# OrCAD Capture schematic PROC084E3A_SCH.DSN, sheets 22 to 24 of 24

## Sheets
22 22. RMII_INTERFACE: size C; title: RMII INTERFACE
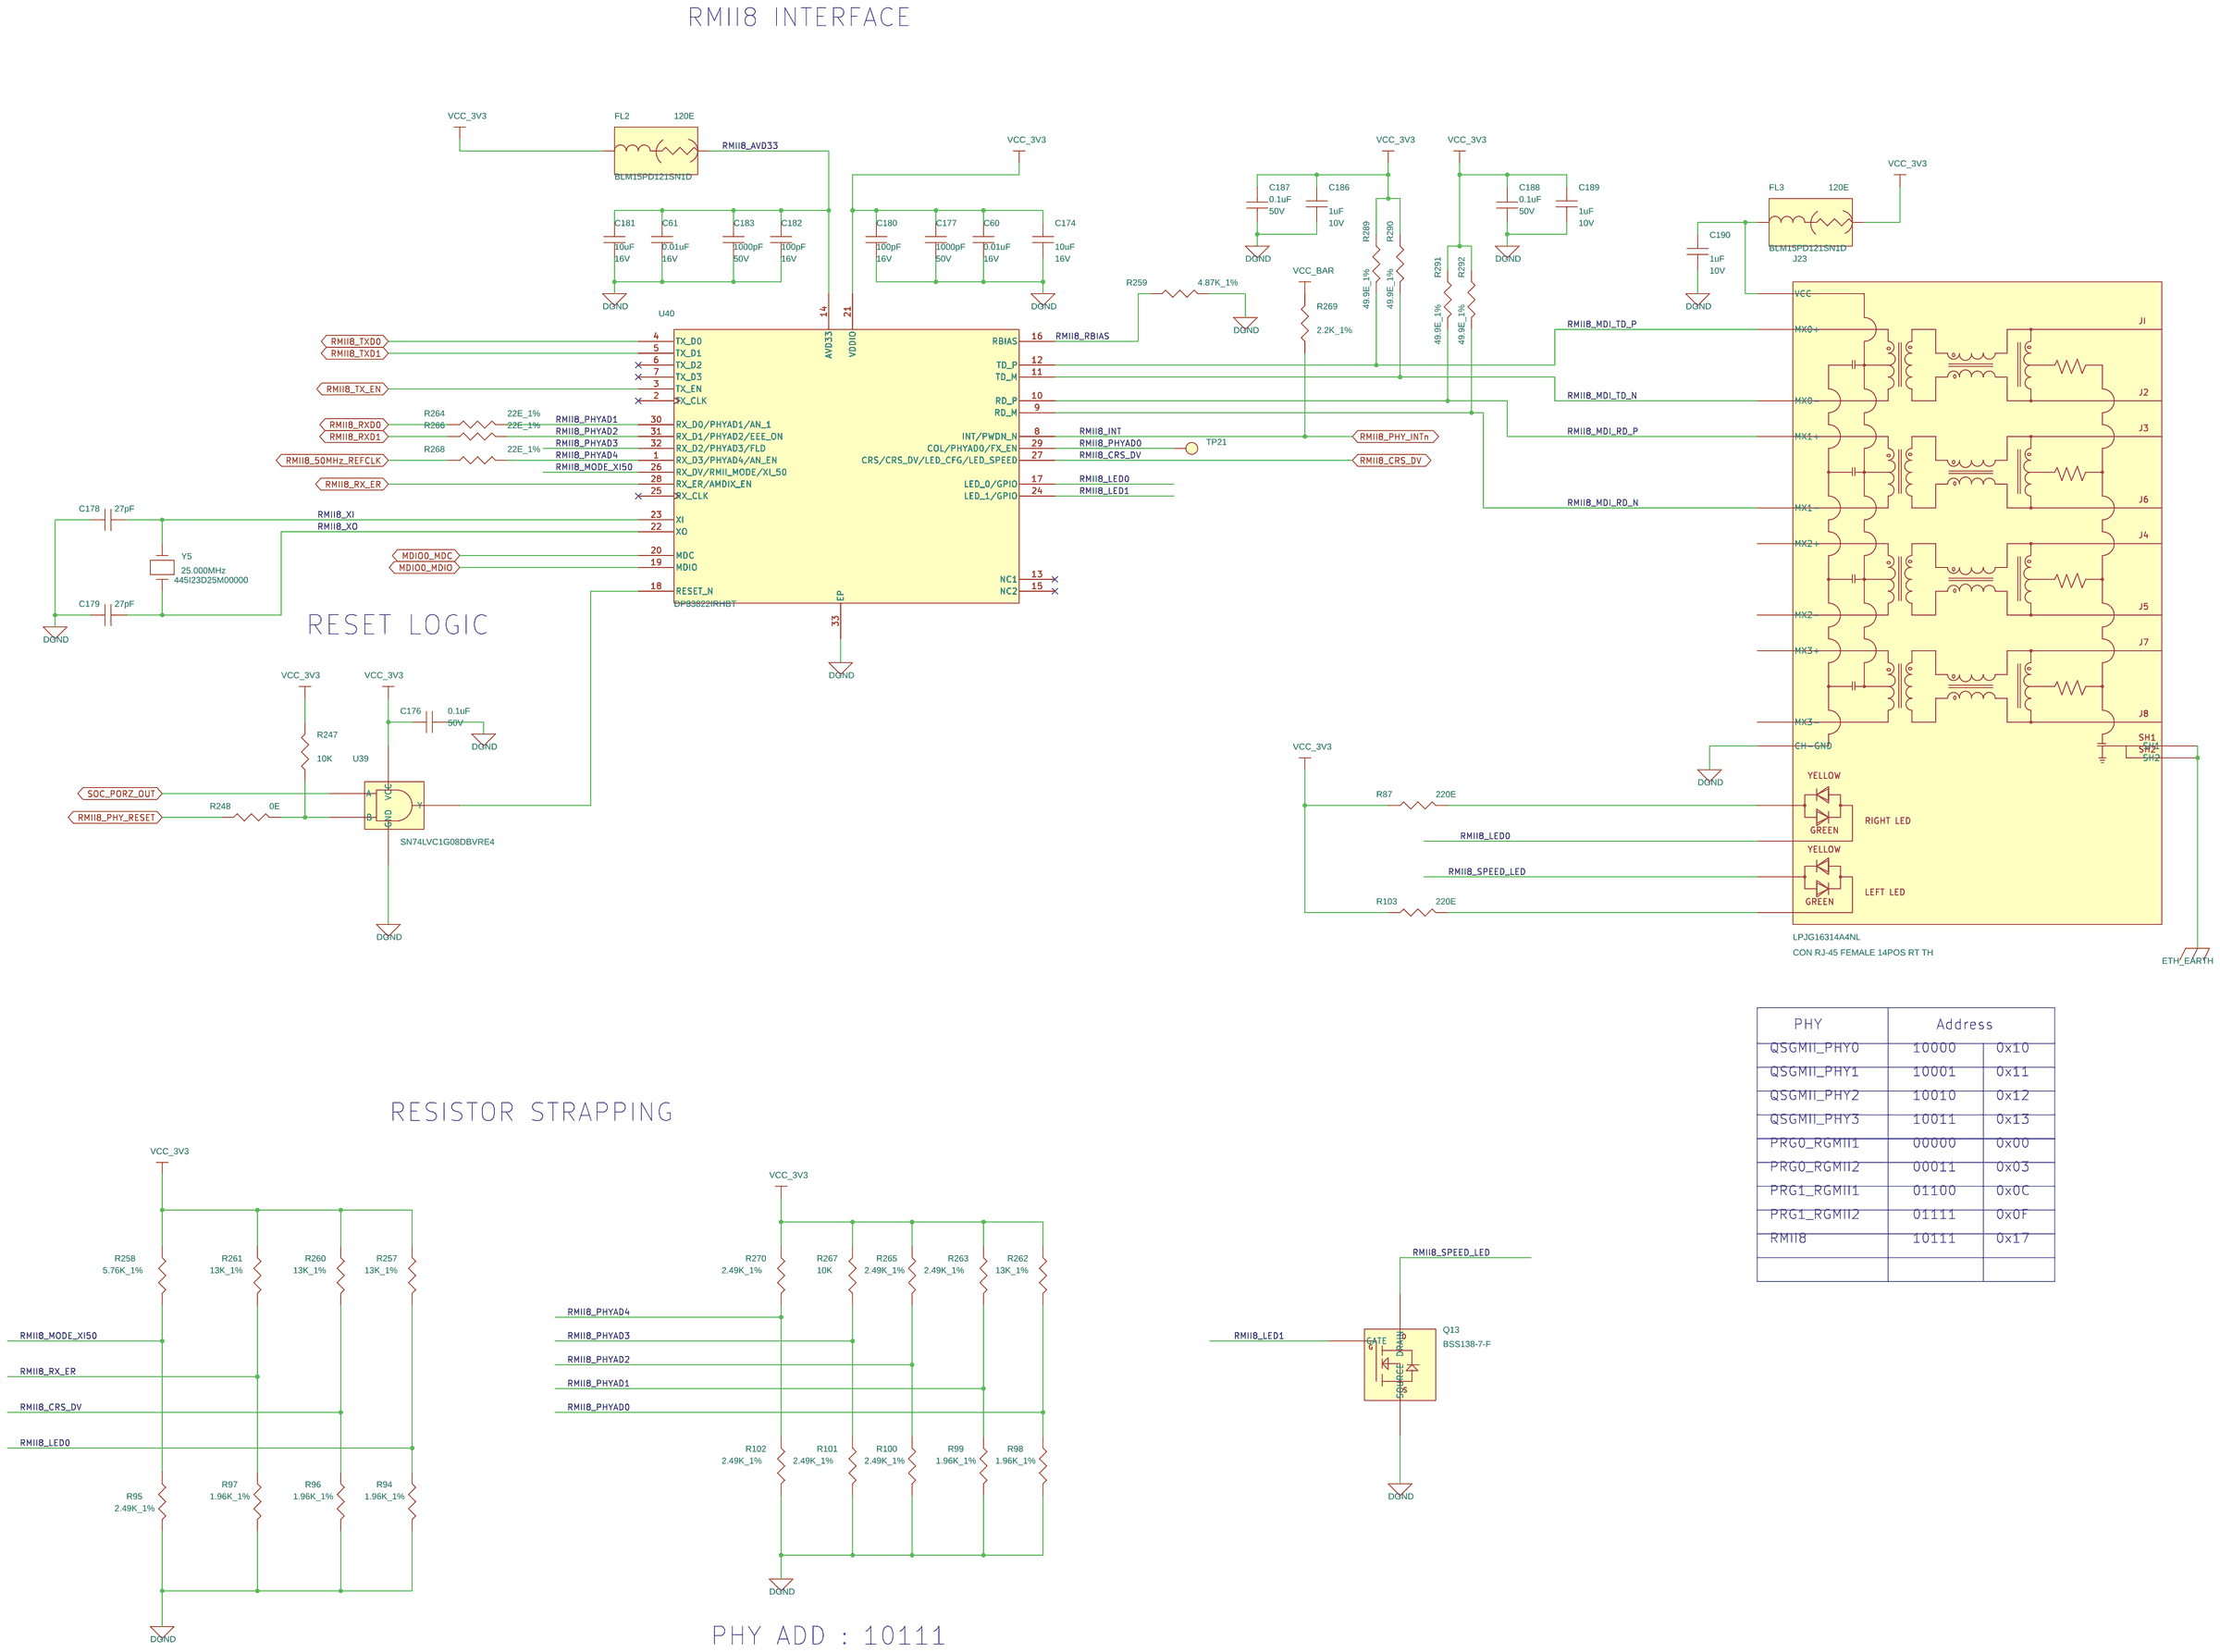
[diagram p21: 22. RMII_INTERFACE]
23 23. POWER SUPPLY: size C; title: P0WER SUPPLY
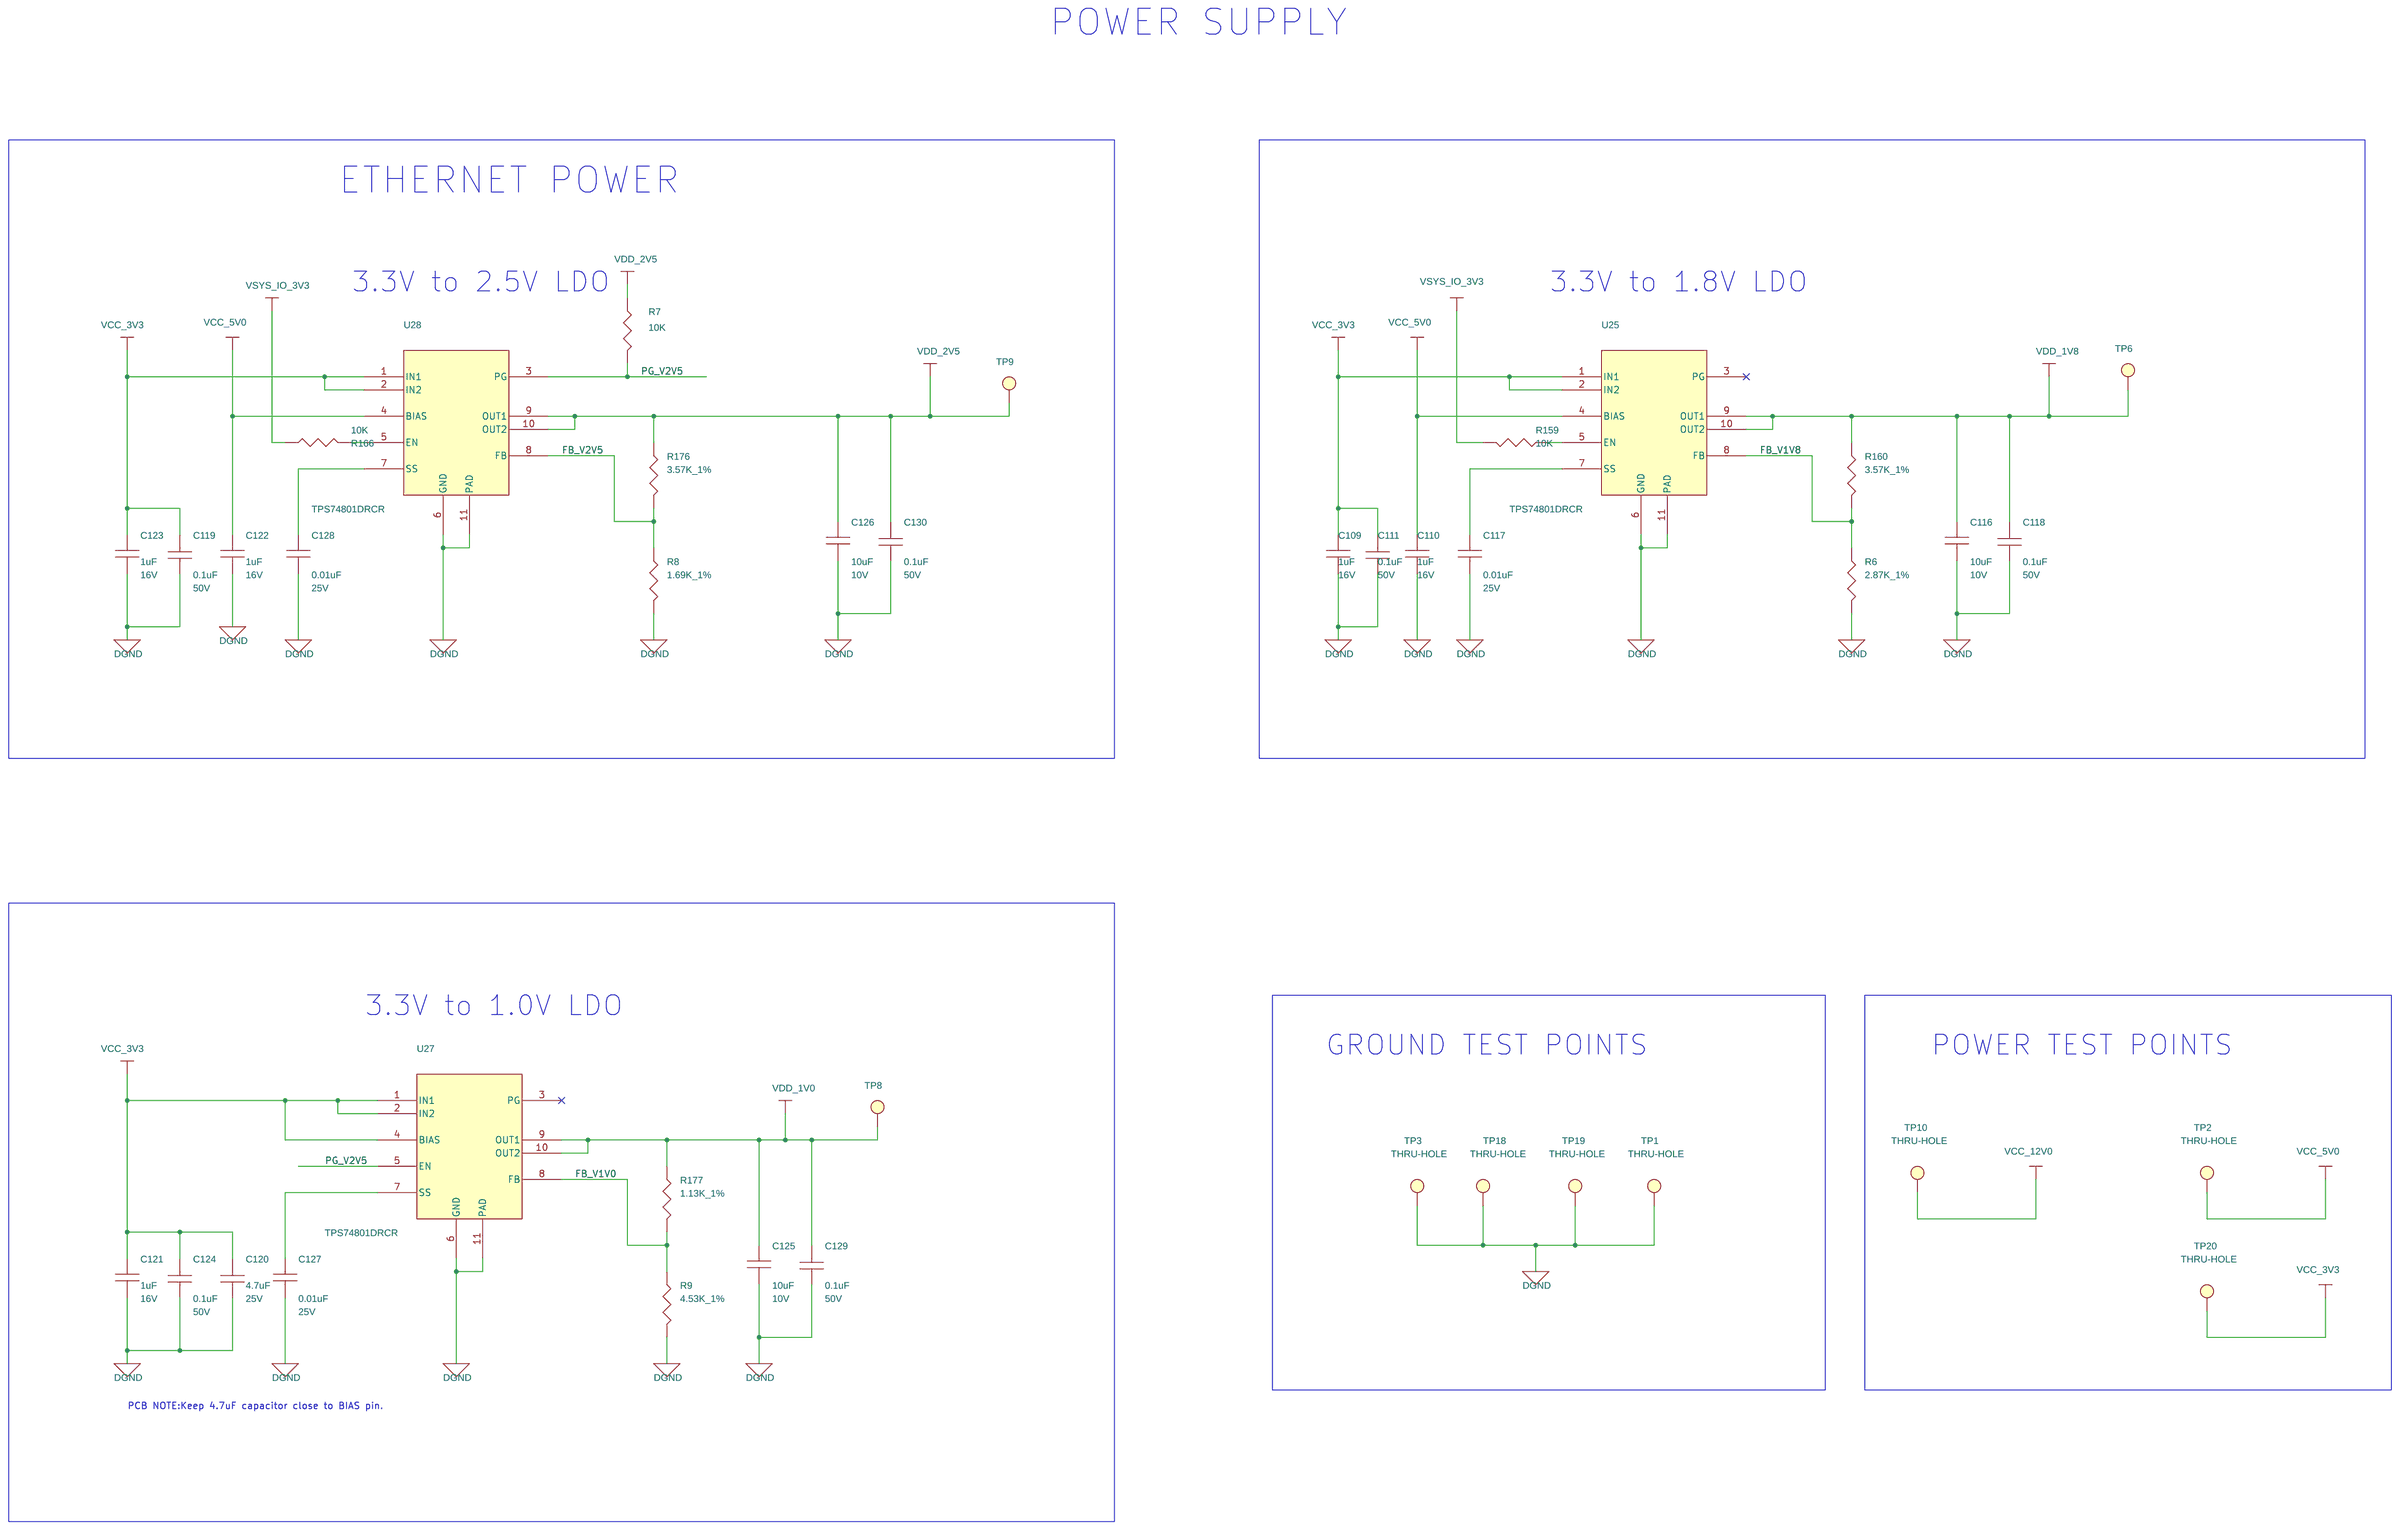
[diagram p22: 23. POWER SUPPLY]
24 19. USS/IMU & MOTOR CONTROL: size C; title: USS/IMU & MOTOR CONTROL
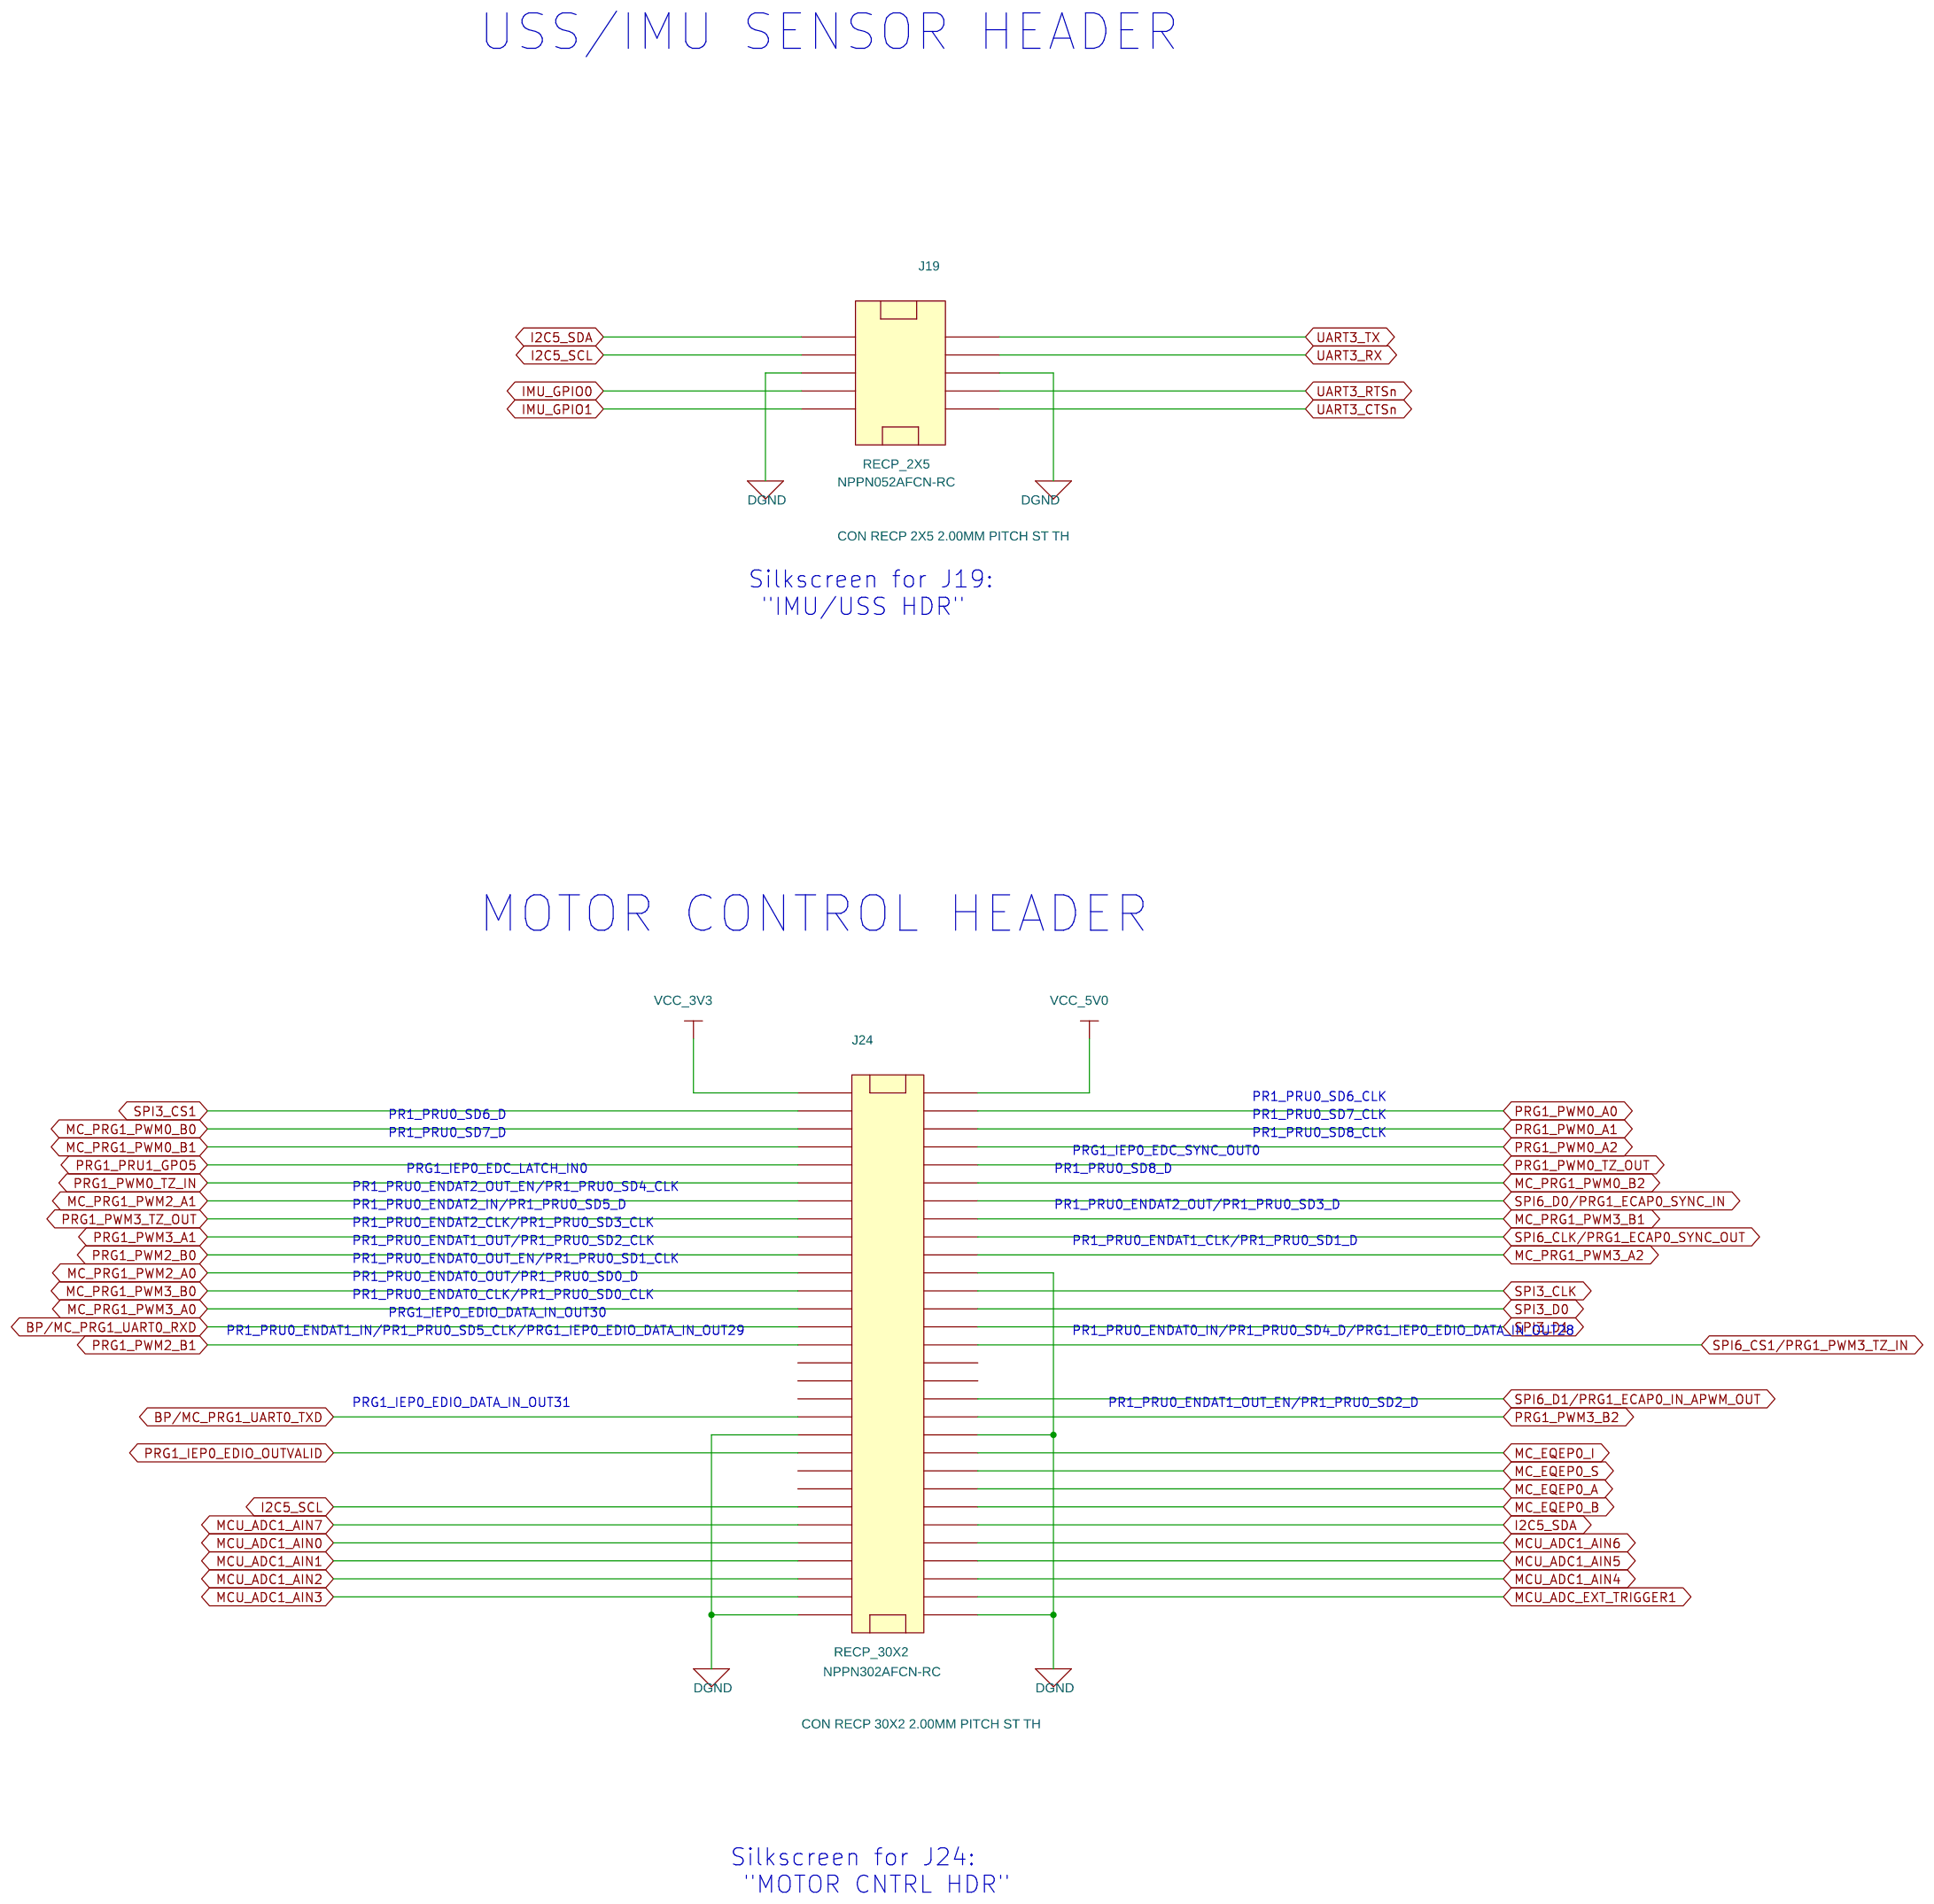
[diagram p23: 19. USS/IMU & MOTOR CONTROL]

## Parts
sheet 19. USS/IMU & MOTOR CONTROL
J19  RECP_2X5  [RECPT_2X5_NPPN052AFCN_S_T_4-3]
J24  RECP_30X2  [RECPT_2X30_78-74_S_T]
sheet 22. RMII_INTERFACE
C60  0.01uF  [CAP0402_0-75]
C61  0.01uF  [CAP0402_0-75]
C174  10uF  [CAP0805_1-5]
C176  0.1uF  [CAP0402_0-75]
C177  1000pF  [CAP0402_0-75]
C178  27pF  [CAP0402_0-75]
C179  27pF  [CAP0402_0-75]
C180  100pF  [CAP0402_0-75]
C181  10uF  [CAP0805_1-5]
C182  100pF  [CAP0402_0-75]
C183  1000pF  [CAP0402_0-75]
C186  1uF  [CAP0402_0-75]
C187  0.1uF  [CAP0402_0-75]
C188  0.1uF  [CAP0402_0-75]
C189  1uF  [CAP0402_0-75]
C190  1uF  [CAP0402_0-75]
FL2  120E  [EMIFIL_BLM15A_0402_0-6]
FL3  120E  [EMIFIL_BLM15A_0402_0-6]
J23  CON_RJ45-14_LPJG16314A4NL  [CON_RJ45-14_LPJG16314A4NL_S_R_T_13-6]
Q13  BSS138-7-F  [SOT23-123_1-1]
R87  220E  [RES0603_0-75]
R94  1.96K_1%  [RES0402_0-5]
R95  2.49K_1%  [RES0402_0-5]
R96  1.96K_1%  [RES0402_0-5]
R97  1.96K_1%  [RES0402_0-5]
R98  1.96K_1%  [RES0402_0-5]
R99  1.96K_1%  [RES0402_0-5]
R100  2.49K_1%  [RES0402_0-5]
R101  2.49K_1%  [RES0402_0-5]
R102  2.49K_1%  [RES0402_0-5]
R103  220E  [RES0603_0-75]
R247  10K  [RES0402_0-5]
R248  0E  [RES0402_0-5]
R257  13K_1%  [RES0402_0-5]
R258  5.76K_1%  [RES0402_0-5]
R259  4.87K_1%  [RES0402_0-5]
R260  13K_1%  [RES0402_0-5]
R261  13K_1%  [RES0402_0-5]
R262  13K_1%  [RES0402_0-5]
R263  2.49K_1%  [RES0402_0-5]
R264  22E_1%  [RES0402_0-5]
R265  2.49K_1%  [RES0402_0-5]
R266  22E_1%  [RES0402_0-5]
R267  10K  [RES0402_0-5]
R268  22E_1%  [RES0402_0-5]
R269  2.2K_1%  [RES0402_0-5]
R270  2.49K_1%  [RES0402_0-5]
R289  49.9E_1%  [RES0402_0-5]
R290  49.9E_1%  [RES0402_0-5]
R291  49.9E_1%  [RES0402_0-5]
R292  49.9E_1%  [RES0402_0-5]
TP21  TP40_SMD  [TP40_SMD]
U39  SN74LVC1G08DBVRE4  [SOT23-5]
U40  DP83822IRHBT  [QFN32_19-68_200X200_1]
Y5  25.000MHz  [XTAL_ABM3_205X130_SMD_1-4]
sheet 23. POWER SUPPLY
C109  1uF  [CAP0402_0-5]
C110  1uF  [CAP0402_0-5]
C111  0.1uF  [CAP0402_0-75]
C116  10uF  [CAP0402_0-75]
C117  0.01uF  [CAP0402_0-75]
C118  0.1uF  [CAP0402_0-75]
C119  0.1uF  [CAP0402_0-75]
C120  4.7uF  [CAP0603_1]
C121  1uF  [CAP0402_0-5]
C122  1uF  [CAP0402_0-5]
C123  1uF  [CAP0402_0-5]
C124  0.1uF  [CAP0402_0-75]
C125  10uF  [CAP0402_0-75]
C126  10uF  [CAP0402_0-75]
C127  0.01uF  [CAP0402_0-75]
C128  0.01uF  [CAP0402_0-75]
C129  0.1uF  [CAP0402_0-75]
C130  0.1uF  [CAP0402_0-75]
R6  2.87K_1%  [RES0402_0-5]
R7  10K  [RES0402_0-5]
R8  1.69K_1%  [RES0402_0-5]
R9  4.53K_1%  [RES0402_0-5]
R159  10K  [RES0402_0-5]
R160  3.57K_1%  [RES0402_0-5]
R166  10K  [RES0402_0-5]
R176  3.57K_1%  [RES0402_0-5]
R177  1.13K_1%  [RES0402_0-5]
TP1  THRU HOLE  [TP_40X65]
TP2  THRU HOLE  [TP_40X65]
TP3  THRU HOLE  [TP_40X65]
TP6  THRU HOLE  [TP_40X65]
TP8  THRU HOLE  [TP_40X65]
TP9  THRU HOLE  [TP_40X65]
TP10  THRU HOLE  [TP_40X65]
TP18  THRU HOLE  [TP_40X65]
TP19  THRU HOLE  [TP_40X65]
TP20  THRU HOLE  [TP_40X65]
U25  TPS74801DRCR  [VSON10_TPS74801-Q1_120X120_1]
U27  TPS74801DRCR  [VSON10_TPS74801-Q1_120X120_1]
U28  TPS74801DRCR  [VSON10_TPS74801-Q1_120X120_1]

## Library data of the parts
J19 = RECP_5X2: CON RECP 2X5 2.00MM PITCH ST TH; Chkd/date: MANIRAJA/281218; Crtd /date: MANIRAJA/281218; Custom_Duty: 24%; Customs_HS_Code: 85369090; Distributor_name: DIGIKEY; Distributor_part_number: S5750-05-ND; Footprint Path: Y:\MIS_DATABASE\Library\ALTIUM_TOOL\PCB_FOOTPRINTS\Altium_Footprint_Lib.PcbLib; Height: 4.30MM; Library Path: Y:\MIS_DATABASE\Library\ALTIUM_TOOL\SCHEMATICS_PARTS\MS_CONNECTOR_Library.schlib; Mfr_name: SULLINS ELECTRONICS; Mfr_part_number: NPPN052AFCN-RC; Mistral Part No: 150018120018-R; Package: THRU-HOLE; Part_type: CONNECTOR\RECEPTACLE; Project: TI_J7ES_GESI_EXP; RoHS: RoHS; Temperature: -40°C+105°C; Tolerance: NA; Voltage: NA; Wattage: NA; Weight: NA; Datasheet: Y:\MIS_DATABASE\DATASHEETS\CONNECTORS\XPPNXX2AFCN-RC.PDF
J24 = RECP_30X2: CON RECP 30X2 2.00MM PITCH ST TH; Chkd/date: NAVEED/060815; Crtd /date: NAVEED/170914; Distributor_name: DIGIKEY; Distributor_part_number: S5750-30-ND; Height: 4.30MM; Mfr_name: SULLINS CONNECTOR; Mfr_part_number: NPPN302AFCN-RC; Mistral Part No: 150014090014-R; Package: THRU-HOLE; Part_type: CONNECTOR\RECEPTACLE; Project: AEGIS_POM; RoHS: RoHS; Temperature: -40°C+105°C; Tolerance: NA; Voltage: NA; Wattage: NA; Weight: NA; Datasheet: Y:\MIS_DATABASE\DATASHEETS\CONNECTORS\NPPNXXX.PDF
C60 C61 = CAP: CAP CERAMIC 0.01uF 16V 5% X7R 0402; Chkd/date: MANIRAJA/160519; Crtd /date: ALVY/160519; Custom_Duty: 15%; Customs_HS_Code: 85322990; Distributor_name: DIGIKEY; Distributor_part_number: 1276-1496-1-ND; Footprint Path: Y:\MIS_DATABASE\Library\ALTIUM_TOOL\PCB_FOOTPRINTS\Altium_Footprint_Lib.PcbLib; Height: 0.55MM; Library Path: Y:\MIS_DATABASE\Library\ALTIUM_TOOL\SCHEMATICS_PARTS\MS_DISCRETE_Library.schlib; Mfr_name: SAMSUNG; Mfr_part_number: CL05B103JO5NNNC; Mistral Part No: 120009030024-R; Package: 0402; Part_type: CAPACITORS\CERAMIC; Project: J7ES_SOM_DUAL-LEO_PMIC; RoHS: RoHS; Temperature: -55°C+125°C; Tolerance: 5%; Voltage: 16V; Wattage: NA; Weight: NA; Datasheet: Y:\MIS_DATABASE\DATASHEETS\CAPACITORS\CL05B103JO5NNNC.PDF
C174 C181 = CAP: CAP CERAMIC 10uF 16V 10% X5R 0805; Chkd/date: SHREESHAIL/220506; Crtd /date: MAZHAR/150506; Custom_Duty: 15%; Customs_HS_Code: 85322990; Distributor_name: DIGIKEY; Distributor_part_number: 490-3886-1-ND; Footprint Path: Y:\MIS_DATABASE\Library\ALTIUM_TOOL\PCB_FOOTPRINTS\Altium_Footprint_Lib.PcbLib; Height: 1.35MM; Library Path: Y:\MIS_DATABASE\Library\ALTIUM_TOOL\SCHEMATICS_PARTS\MS_DISCRETE_Library.schlib; Mfr_name: MURATA; Mfr_part_number: GRM21BR61C106KE15L; Mistral Part No: 120009030205-R; Package: 0805; Part_type: CAPACITORS\CERAMIC; Project: VOCERA; RoHS: RoHS; Temperature: -55°C+85°C; Tolerance: 10%; Voltage: 16V; Wattage: NA; Weight: 9.5mg; Datasheet: Y:\MIS_DATABASE\DATASHEETS\CAPACITORS\MURATA-GXX-SER_NOV17.PDF
C111 C118 C119 C124 C129 C130 C176 C187 C188 = CAP: CAP CERAMIC 0.1uF 50V 10% X7R 0402; Chkd/date: VASANTHA/281216; Crtd /date: CHAITHANYA/051011; Custom_Duty: 15%; Customs_HS_Code: 85322990; Distributor_name: DIGIKEY; Distributor_part_number: 445-173610-1-ND; Footprint Path: Y:\MIS_DATABASE\Library\ALTIUM_TOOL\PCB_FOOTPRINTS\Altium_Footprint_Lib.PcbLib; Height: 0.60MM; Library Path: Y:\MIS_DATABASE\Library\ALTIUM_TOOL\SCHEMATICS_PARTS\MS_DISCRETE_Library.schlib; Mfr_name: TDK CORPORATION; Mfr_part_number: C1005X7R1H104K050BE; Mistral Part No: 120011100014-R; Package: 0402; Part_type: CAPACITORS\CERAMIC; Project: VP-4000-BASE-BOARD; RoHS: RoHS; Temperature: -55°C+125°C; Tolerance: 10%; Voltage: 50V; Wattage: NA; Weight: 0.65mg; Datasheet: Y:\MIS_DATABASE\DATASHEETS\CAPACITORS\TDK_C-SER_FEB19.PDF
C177 C183 = CAP: CAP CERAMIC 1000pF 50V 5% X7R 0402; Chkd/date: VASANTHA/231216; Crtd /date: BAVISH/090611; Custom_Duty: 15%; Customs_HS_Code: 85322990; Distributor_name: DIGIKEY; Distributor_part_number: 478-3661-1-ND; Footprint Path: Y:\MIS_DATABASE\Library\ALTIUM_TOOL\PCB_FOOTPRINTS\Altium_Footprint_Lib.PcbLib; Height: 0.56MM; Library Path: Y:\MIS_DATABASE\Library\ALTIUM_TOOL\SCHEMATICS_PARTS\MS_DISCRETE_Library.schlib; Mfr_name: AVX CORPORATION; Mfr_part_number: 04025C102JAT2A; Mistral Part No: 120013100001-R; Package: 0402; Part_type: CAPACITORS\CERAMIC; Project: CENTAURUS_LCD-ADAPTER; RoHS: RoHS; Temperature: -55°C+125°C; Tolerance: 5%; Voltage: 50V; Wattage: NA; Weight: 0.65mg; Datasheet: Y:\MIS_DATABASE\DATASHEETS\CAPACITORS\AVX_MLC.PDF
C178 C179 = CAP: CAP CERAMIC 27pF 50V 5% C0G(NP0) 0402; Chkd/date: MAZHAR/241208; Crtd /date: GEETHA/090606; Custom_Duty: 15%; Customs_HS_Code: 85322990; Distributor_name: DIGIKEY; Distributor_part_number: 311-1019-1-ND; Footprint Path: Y:\MIS_DATABASE\Library\ALTIUM_TOOL\PCB_FOOTPRINTS\Altium_Footprint_Lib.PcbLib; Height: 0.55MM; Library Path: Y:\MIS_DATABASE\Library\ALTIUM_TOOL\SCHEMATICS_PARTS\MS_DISCRETE_Library.schlib; Mfr_name: YAGEO AMERICA; Mfr_part_number: CC0402JRNPO9BN270; Mistral Part No: 120014100024-R; Package: 0402; Part_type: CAPACITORS\CERAMIC; Project: PNAV; RoHS: RoHS; Temperature: -55°C+125°C; Tolerance: 5%; Voltage: 50V; Wattage: NA; Weight: 0.65mg; Datasheet: Y:\MIS_DATABASE\DATASHEETS\CAPACITORS\YACC-NPO.PDF
C180 C182 = CAP: CAP CERAMIC 100pF 16V 10% X7R 0402; Chkd/date: VASANTHA/091215; Crtd /date: VASANTHA/091215; Custom_Duty: 15%; Customs_HS_Code: 85322990; Distributor_name: DIGIKEY; Distributor_part_number: 478-7887-1-ND; Footprint Path: Y:\MIS_DATABASE\Library\ALTIUM_TOOL\PCB_FOOTPRINTS\Altium_Footprint_Lib.PcbLib; Height: 0.56MM; Library Path: Y:\MIS_DATABASE\Library\ALTIUM_TOOL\SCHEMATICS_PARTS\MS_DISCRETE_Library.schlib; Mfr_name: AVX CORPORATION; Mfr_part_number: 0402YC101KAT2A; Mistral Part No: 120015120003-R; Package: 0402; Part_type: CAPACITORS\CERAMIC; Project: TI_VLAN_SWITCH; RoHS: RoHS; Temperature: -55°C+125°C; Tolerance: 10%; Voltage: 16V; Wattage: NA; Weight: 0.65mg; Datasheet: Y:\MIS_DATABASE\DATASHEETS\CAPACITORS\AVX_MLC.PDF
C186 C189 C190 = CAP: CAP CERAMIC 1uF 10V 10% X5R 0402; Chkd/date: MANIRAJA/020718; Crtd /date: SARANYA/060514; Custom_Duty: 15%; Customs_HS_Code: 85322990; Distributor_name: DIGIKEY; Distributor_part_number: 478-4596-1-ND; Footprint Path: Y:\MIS_DATABASE\Library\ALTIUM_TOOL\PCB_FOOTPRINTS\Altium_Footprint_Lib.PcbLib; Height: 0.56MM; Library Path: Y:\MIS_DATABASE\Library\ALTIUM_TOOL\SCHEMATICS_PARTS\MS_DISCRETE_Library.schlib; Mfr_name: AVX CORPORATION; Mfr_part_number: 0402ZD105KAT2A; Mistral Part No: 120014050010-R; Package: 0402; Part_type: CAPACITORS\CERAMIC; Project: AEGIS GP BETA2; RoHS: RoHS; Temperature: -55°C+85°C; Tolerance: 10%; Voltage: 10V; Wattage: NA; Weight: 0.65mg; Datasheet: Y:\MIS_DATABASE\DATASHEETS\CAPACITORS\AVX_MLC.PDF
FL2 FL3 = EMIFILTER_IND: IND FERRITE BEAD CHIP 120E 1.3A 0402; Chkd/date: VASANTHA/010117; Crtd /date: CHAITHANYA/150312; Custom_Duty: 24%; Customs_HS_Code: 85437099; Distributor_name: DIGIKEY; Distributor_part_number: 490-5203-1-ND; Footprint Path: Y:\MIS_DATABASE\Library\ALTIUM_TOOL\PCB_FOOTPRINTS\Altium_Footprint_Lib.PcbLib; Height: 0.55MM; Library Path: Y:\MIS_DATABASE\Library\ALTIUM_TOOL\SCHEMATICS_PARTS\MS_FILTER_Library.schlib; Mfr_name: MURATA; Mfr_part_number: BLM15PD121SN1D; Mistral Part No: 130012030043-R; Package: 0402; Part_type: FILTER; Project: GEN_3-8; RoHS: RoHS; Temperature: -55°C+125°C; Tolerance: 25%; Voltage: NA; Wattage: NA; Weight: 0.65mg; Datasheet: Y:\MIS_DATABASE\DATASHEETS\DISCRETES\INDUCTORS\BLM15X-SER.PDF
J23 = CON_RJ45-14_LPJG16314A4NL: CON RJ-45 FEMALE 14POS RT TH; Chkd/date: VASANTHA/150714; Crtd /date: BALACHANDAR/120614; Custom_Duty: 24%; Customs_HS_Code: 85369090; Distributor_name: NA; Distributor_part_number: NA; Footprint Path: Y:\MIS_DATABASE\Library\ALTIUM_TOOL\PCB_FOOTPRINTS\Altium_Footprint_Lib.PcbLib; Height: 13.60MM; Library Path: Y:\MIS_DATABASE\Library\ALTIUM_TOOL\SCHEMATICS_PARTS\MS_CONNECTOR_Library.schlib; Mfr_name: LINK-PP; Mfr_part_number: LPJG16314A4NL; Mistral Part No: 150014060029-R; Package: THRU-HOLE; Part_type: CONNECTOR\JACK; Project: AEGIS; RoHS: RoHS; Temperature: -0°C+70°C; Tolerance: NA; Voltage: NA; Wattage: NA; Weight: NA; Datasheet: Y:\MIS_DATABASE\DATASHEETS\CONNECTORS\LPJG16314A4NL.PDF
Q13 = MOSFET_2N7002_SOT23: IC MOSFET N-CHANNEL 50V 200mA SOT23-123; Chkd/date: MANIRAJA/190618; Crtd /date: USMAN/240709; Custom_Duty: 15%; Customs_HS_Code: 85423100; Distributor_name: DIGIKEY; Distributor_part_number: BSS138-FDICT-ND; Footprint Path: Y:\MIS_DATABASE\Library\ALTIUM_TOOL\PCB_FOOTPRINTS\Altium_Footprint_Lib.PcbLib; Height: 1.10MM; Library Path: Y:\MIS_DATABASE\Library\ALTIUM_TOOL\SCHEMATICS_PARTS\MS_MOSFET_Library.schlib; Mfr_name: DIODES INC; Mistral Part No: 142009070019-R; Package: SOT23-123; Part_type: ICS\POWER\MOSFET; Project: KHAN_MAIN; RoHS: RoHS; Temperature: -55°C+150°C; Tolerance: NA; Voltage: 50V; Wattage: 300mW; Weight: 8mg; Datasheet: Y:\MIS_DATABASE\DATASHEETS\DISCRETES\TRANSISTORS_FETS\BSS138.PDF
R87 R103 = RESISTOR: RES 220E 1/4W 5% 0603 (HP); Chkd/date: MAZHAR/251010; Crtd /date: BAVISH/141010; Custom_Duty: 15%; Customs_HS_Code: 85332119; Distributor_name: DIGIKEY; Distributor_part_number: 541-220SACT-ND; Footprint Path: Y:\MIS_DATABASE\Library\ALTIUM_TOOL\PCB_FOOTPRINTS\Altium_Footprint_Lib.PcbLib; Height: 0.55MM; Library Path: Y:\MIS_DATABASE\Library\ALTIUM_TOOL\SCHEMATICS_PARTS\MS_DISCRETE_Library.schlib; Mfr_name: VISHAY; Mfr_part_number: CRCW0603220RJNEAHP; Mistral Part No: 110010100005-R; Package: 0603; Part_type: RESISTORS\FIXED; Project: AAAUC; RoHS: RoHS; Temperature: -55°C+155°C; Tolerance: 5%; Voltage: NA; Wattage: 1/4W; Weight: 2mg; Datasheet: Y:\MIS_DATABASE\DATASHEETS\RESISTORS\CRCWXXX-HP_SEP16.PDF
R94 R97-R99 = RESISTOR: RES 1.96K 1/10W 1% 0402; Assembly_Instruction: DNI; Chkd/date: JEBRAN/260315; Crtd /date: USMAN/121012; Custom_Duty: 15%; Customs_HS_Code: 85332119; Distributor_name: DIGIKEY; Distributor_part_number: P1.96KLCT-ND; Footprint Path: Y:\MIS_DATABASE\Library\ALTIUM_TOOL\PCB_FOOTPRINTS\Altium_Footprint_Lib.PcbLib; Height: 0.40MM; Library Path: Y:\MIS_DATABASE\Library\ALTIUM_TOOL\SCHEMATICS_PARTS\MS_DISCRETE_Library.schlib; Mfr_name: PANASONIC-ECG; Mfr_part_number: ERJ-2RKF1961X; Mistral Part No: 110012100019-R; Package: 0402; Part_type: RESISTORS\FIXED; Project: ITS-CONTROLER_CARD; RoHS: RoHS; SIGNAL_MODEL: RESISTOR_RES0402_1.96K_1%_1.96K_1%; Temperature: -55°C+155°C; Tolerance: 1%; Voltage: NA; Wattage: 1/10W; Weight: 0.8mg; Datasheet: Y:\MIS_DATABASE\DATASHEETS\RESISTORS\PAN-ERJSER_NOV17.PDF
R95 R100 R101 = RESISTOR: RES 2.49K 1/16W 1% 0402; Assembly_Instruction: DNI; Chkd/date: VASANTHA/270516; Crtd /date: VASANTHA/270516; Custom_Duty: 15%; Customs_HS_Code: 85332119; Distributor_name: DIGIKEY; Distributor_part_number: 311-2.49KLRCT-ND; Footprint Path: Y:\MIS_DATABASE\Library\ALTIUM_TOOL\PCB_FOOTPRINTS\Altium_Footprint_Lib.PcbLib; Height: 0.40MM; Library Path: Y:\MIS_DATABASE\Library\ALTIUM_TOOL\SCHEMATICS_PARTS\MS_DISCRETE_Library.schlib; Mfr_name: YAGEO AMERICA; Mfr_part_number: RC0402FR-072K49L; Mistral Part No: 110016050020-R; Package: 0402; Part_type: RESISTORS\FIXED; Project: TMDXCSKCC; RoHS: RoHS; SIGNAL_MODEL: RESISTOR_RES0402_2.49K_1%_2.49K_1%; Temperature: -55°C+155°C; Tolerance: 1%; Voltage: NA; Wattage: 1/16W; Weight: 0.65mg; Datasheet: Y:\MIS_DATABASE\DATASHEETS\RESISTORS\RCXXXXL-SER_MAR18.PDF
R96 = RESISTOR: RES 1.96K 1/10W 1% 0402; Chkd/date: JEBRAN/260315; Crtd /date: USMAN/121012; Custom_Duty: 15%; Customs_HS_Code: 85332119; Distributor_name: DIGIKEY; Distributor_part_number: P1.96KLCT-ND; Footprint Path: Y:\MIS_DATABASE\Library\ALTIUM_TOOL\PCB_FOOTPRINTS\Altium_Footprint_Lib.PcbLib; Height: 0.40MM; Library Path: Y:\MIS_DATABASE\Library\ALTIUM_TOOL\SCHEMATICS_PARTS\MS_DISCRETE_Library.schlib; Mfr_name: PANASONIC-ECG; Mfr_part_number: ERJ-2RKF1961X; Mistral Part No: 110012100019-R; Package: 0402; Part_type: RESISTORS\FIXED; Project: ITS-CONTROLER_CARD; RoHS: RoHS; SIGNAL_MODEL: RESISTOR_RES0402_1.96K_1%_1.96K_1%; Temperature: -55°C+155°C; Tolerance: 1%; Voltage: NA; Wattage: 1/10W; Weight: 0.8mg; Datasheet: Y:\MIS_DATABASE\DATASHEETS\RESISTORS\PAN-ERJSER_NOV17.PDF
R102 = RESISTOR: RES 2.49K 1/16W 1% 0402; Assembly_Instruction: DNI; Chkd/date: VASANTHA/270516; Crtd /date: VASANTHA/270516; Custom_Duty: 15%; Customs_HS_Code: 85332119; Distributor_name: DIGIKEY; Distributor_part_number: 311-2.49KLRCT-ND; Footprint Path: Y:\MIS_DATABASE\Library\ALTIUM_TOOL\PCB_FOOTPRINTS\Altium_Footprint_Lib.PcbLib; Height: 0.40MM; Library Path: Y:\MIS_DATABASE\Library\ALTIUM_TOOL\SCHEMATICS_PARTS\MS_DISCRETE_Library.schlib; Mfr_name: YAGEO AMERICA; Mfr_part_number: RC0402FR-072K49L; Mistral Part No: 110016050020-R; Package: 0402; Part_type: RESISTORS\FIXED; Project: TMDXCSKCC; RoHS: RoHS; Temperature: -55°C+155°C; Tolerance: 1%; Voltage: NA; Wattage: 1/16W; Weight: 0.65mg; Datasheet: Y:\MIS_DATABASE\DATASHEETS\RESISTORS\RCXXXXL-SER_MAR18.PDF
R7 R159 R166 R247 = RESISTOR: RES 10K 1/16W 5% 0402; Chkd/date: VASANTHA/061216; Crtd /date: MAZHAR/230805; Custom_Duty: 15%; Customs_HS_Code: 85332119; Distributor_name: DIGIKEY; Distributor_part_number: 311-10KJRCT-ND; Footprint Path: Y:\MIS_DATABASE\Library\ALTIUM_TOOL\PCB_FOOTPRINTS\Altium_Footprint_Lib.PcbLib; Height: 0.40MM; Library Path: Y:\MIS_DATABASE\Library\ALTIUM_TOOL\SCHEMATICS_PARTS\MS_DISCRETE_Library.schlib; Mfr_name: YAGEO AMERICA; Mfr_part_number: RC0402JR-0710KL; Mistral Part No: 110011060021-R; Package: 0402; Part_type: RESISTORS\FIXED; Project: HSE; RoHS: RoHS; Temperature: -55°C+155°C; Tolerance: 5%; Voltage: NA; Wattage: 1/16W; Weight: 0.65mg; Datasheet: Y:\MIS_DATABASE\DATASHEETS\RESISTORS\RCXXXXL-SER_MAR18.PDF
R248 = RESISTOR: RES 0E 1/10W JUMPER 0402; Chkd/date: MANIRAJA/290318; Crtd /date: ALVY/270318; Custom_Duty: 15%; Customs_HS_Code: 85332119; Distributor_name: DIGIKEY; Distributor_part_number: MCS0402-0.0-ZZCT-ND; Footprint Path: Y:\MIS_DATABASE\Library\ALTIUM_TOOL\PCB_FOOTPRINTS\Altium_Footprint_Lib.PcbLib; Height: 0.37MM; Library Path: Y:\MIS_DATABASE\Library\ALTIUM_TOOL\SCHEMATICS_PARTS\MS_DISCRETE_Library.schlib; Mfr_name: VISHAY; Mfr_part_number: MCS04020Z0000ZE000; Mistral Part No: 110018030052-R; Package: 0402; Part_type: RESISTORS\FIXED; Project: DRDL_ITS2-SC; RoHS: RoHS; SIGNAL_MODEL: INS23888567; Temperature: -55°C+155°C; Tolerance: NA; Voltage: NA; Wattage: 1/10W; Weight: 0.65mg; Datasheet: Y:\MIS_DATABASE\DATASHEETS\RESISTORS\MCTXXXXC-SER.PDF
R257 R261 R262 = RESISTOR: RES 13K 1/10W 1% 0402; Assembly_Instruction: DNI; Chkd/date: USMAN/200613; Crtd /date: USMAN/310513; Custom_Duty: 15%; Customs_HS_Code: 85332119; Distributor_name: DIGIKEY; Distributor_part_number: P13.0KLCT-ND; Footprint Path: Y:\MIS_DATABASE\Library\ALTIUM_TOOL\PCB_FOOTPRINTS\Altium_Footprint_Lib.PcbLib; Height: 0.40MM; Library Path: Y:\MIS_DATABASE\Library\ALTIUM_TOOL\SCHEMATICS_PARTS\MS_DISCRETE_Library.schlib; Mfr_name: PANASONIC-ECG; Mfr_part_number: ERJ-2RKF1302X; Mistral Part No: 110013050013-R; Package: 0402; Part_type: RESISTORS\FIXED; Project: DTRM; RoHS: RoHS; Temperature: -55°C+155°C; Tolerance: 1%; Voltage: NA; Wattage: 1/10W; Weight: 0.8mg; Datasheet: Y:\MIS_DATABASE\DATASHEETS\RESISTORS\PAN-ERJSER_NOV17.PDF
R258 = RESISTOR: RES 5.76K 1/10W 1% 0402; Chkd/date: MAZHAR/150709; Crtd /date: USMAN/220808; Custom_Duty: 15%; Customs_HS_Code: 85332119; Distributor_name: DIGIKEY; Distributor_part_number: P5.76KLCT-ND; Footprint Path: Y:\MIS_DATABASE\Library\ALTIUM_TOOL\PCB_FOOTPRINTS\Altium_Footprint_Lib.PcbLib; Height: 0.40MM; Library Path: Y:\MIS_DATABASE\Library\ALTIUM_TOOL\SCHEMATICS_PARTS\MS_DISCRETE_Library.schlib; Mfr_name: PANASONIC-ECG; Mfr_part_number: ERJ-2RKF5761X; Mistral Part No: 110009030945-R; Package: 0402; Part_type: RESISTORS\FIXED; Project: CPB; RoHS: RoHS; Temperature: -55°C+155°C; Tolerance: 1%; Voltage: NA; Wattage: 1/10W; Weight: 0.8mg; Datasheet: Y:\MIS_DATABASE\DATASHEETS\RESISTORS\PAN-ERJSER_NOV17.PDF
R259 = RESISTOR: RES 4.87K 1/10W 1% 0402; Chkd/date: MAZHAR/150709; Crtd /date: USMAN/150109; Custom_Duty: 15%; Customs_HS_Code: 85332119; Distributor_name: DIGIKEY; Distributor_part_number: P4.87KLCT-ND; Footprint Path: Y:\MIS_DATABASE\Library\ALTIUM_TOOL\PCB_FOOTPRINTS\Altium_Footprint_Lib.PcbLib; Height: 0.40MM; Library Path: Y:\MIS_DATABASE\Library\ALTIUM_TOOL\SCHEMATICS_PARTS\MS_DISCRETE_Library.schlib; Mfr_name: PANASONIC-ECG; Mfr_part_number: ERJ-2RKF4871X; Mistral Part No: 110009030803-R; Package: 0402; Part_type: RESISTORS\FIXED; Project: BSN-II; RoHS: RoHS; Temperature: -55°C+155°C; Tolerance: 1%; Voltage: NA; Wattage: 1/10W; Weight: 0.8mg; Datasheet: Y:\MIS_DATABASE\DATASHEETS\RESISTORS\PAN-ERJSER_NOV17.PDF
R260 = RESISTOR: RES 13K 1/10W 1% 0402; Chkd/date: USMAN/200613; Crtd /date: USMAN/310513; Custom_Duty: 15%; Customs_HS_Code: 85332119; Distributor_name: DIGIKEY; Distributor_part_number: P13.0KLCT-ND; Footprint Path: Y:\MIS_DATABASE\Library\ALTIUM_TOOL\PCB_FOOTPRINTS\Altium_Footprint_Lib.PcbLib; Height: 0.40MM; Library Path: Y:\MIS_DATABASE\Library\ALTIUM_TOOL\SCHEMATICS_PARTS\MS_DISCRETE_Library.schlib; Mfr_name: PANASONIC-ECG; Mfr_part_number: ERJ-2RKF1302X; Mistral Part No: 110013050013-R; Package: 0402; Part_type: RESISTORS\FIXED; Project: DTRM; RoHS: RoHS; Temperature: -55°C+155°C; Tolerance: 1%; Voltage: NA; Wattage: 1/10W; Weight: 0.8mg; Datasheet: Y:\MIS_DATABASE\DATASHEETS\RESISTORS\PAN-ERJSER_NOV17.PDF
R263 R265 = RESISTOR: RES 2.49K 1/16W 1% 0402; Chkd/date: VASANTHA/270516; Crtd /date: VASANTHA/270516; Custom_Duty: 15%; Customs_HS_Code: 85332119; Distributor_name: DIGIKEY; Distributor_part_number: 311-2.49KLRCT-ND; Footprint Path: Y:\MIS_DATABASE\Library\ALTIUM_TOOL\PCB_FOOTPRINTS\Altium_Footprint_Lib.PcbLib; Height: 0.40MM; Library Path: Y:\MIS_DATABASE\Library\ALTIUM_TOOL\SCHEMATICS_PARTS\MS_DISCRETE_Library.schlib; Mfr_name: YAGEO AMERICA; Mfr_part_number: RC0402FR-072K49L; Mistral Part No: 110016050020-R; Package: 0402; Part_type: RESISTORS\FIXED; Project: TMDXCSKCC; RoHS: RoHS; SIGNAL_MODEL: RESISTOR_RES0402_2.49K_1%_2.49K_1%; Temperature: -55°C+155°C; Tolerance: 1%; Voltage: NA; Wattage: 1/16W; Weight: 0.65mg; Datasheet: Y:\MIS_DATABASE\DATASHEETS\RESISTORS\RCXXXXL-SER_MAR18.PDF
R264 R266 R268 = RESISTOR: RES 22E 1/16W 1% 0402; Chkd/date: SUHAS/290910; Crtd /date: MAZHAR/090909; Cust_part_number: 4700-80047E; Custom_Duty: 15%; Customs_HS_Code: 85332119; Distributor_name: DIGIKEY; Distributor_part_number: 311-22.0LRCT-ND; Footprint Path: Y:\MIS_DATABASE\Library\ALTIUM_TOOL\PCB_FOOTPRINTS\Altium_Footprint_Lib.PcbLib; Height: 0.40MM; Library Path: Y:\MIS_DATABASE\Library\ALTIUM_TOOL\SCHEMATICS_PARTS\MS_DISCRETE_Library.schlib; Mfr_name: YAGEO AMERICA; Mfr_part_number: RC0402FR-0722RL; Mistral Part No: 110009090004-R; Package: 0402; Part_type: RESISTORS\FIXED; Project: VMEFMCD; RoHS: RoHS; SIGNAL_MODEL: RESISTOR_RES0402_22E_1%_22E_1%; Temperature: -55°C+155°C; Tolerance: 1%; Voltage: NA; Wattage: 1/16W; Weight: 0.65mg; Datasheet: Y:\MIS_DATABASE\DATASHEETS\RESISTORS\RCXXXXL-SER_MAR18.PDF
R267 = RESISTOR: RES 10K 1/16W 5% 0402; Assembly_Instruction: DNI; Chkd/date: VASANTHA/061216; Crtd /date: MAZHAR/230805; Custom_Duty: 15%; Customs_HS_Code: 85332119; Distributor_name: DIGIKEY; Distributor_part_number: 311-10KJRCT-ND; Footprint Path: Y:\MIS_DATABASE\Library\ALTIUM_TOOL\PCB_FOOTPRINTS\Altium_Footprint_Lib.PcbLib; Height: 0.40MM; Library Path: Y:\MIS_DATABASE\Library\ALTIUM_TOOL\SCHEMATICS_PARTS\MS_DISCRETE_Library.schlib; Mfr_name: YAGEO AMERICA; Mfr_part_number: RC0402JR-0710KL; Mistral Part No: 110011060021-R; Package: 0402; Part_type: RESISTORS\FIXED; Project: HSE; RoHS: RoHS; SIGNAL_MODEL: RESISTOR_RES0402_0-5_10K_10K; Temperature: -55°C+155°C; Tolerance: 5%; Voltage: NA; Wattage: 1/16W; Weight: 0.65mg; Datasheet: Y:\MIS_DATABASE\DATASHEETS\RESISTORS\RCXXXXL-SER_MAR18.PDF
R269 = RESISTOR: RES 2.2K 1/16W 1% 0402; Chkd/date: VASANTHA/170217; Crtd /date: VASANTHA/101114; Cust_part_number: 4700-80113E; Custom_Duty: 15%; Customs_HS_Code: 85332119; Distributor_name: DIGIKEY; Distributor_part_number: 311-2.20KLRCT-ND; Footprint Path: Y:\MIS_DATABASE\Library\ALTIUM_TOOL\PCB_FOOTPRINTS\Altium_Footprint_Lib.PcbLib; Height: 0.40MM; Library Path: Y:\MIS_DATABASE\Library\ALTIUM_TOOL\SCHEMATICS_PARTS\MS_DISCRETE_Library.schlib; Mfr_name: YAGEO AMERICA; Mfr_part_number: RC0402FR-072K2L; Mistral Part No: 110014110004-R; Package: 0402; Part_type: RESISTORS\FIXED; Project: GALILEO_EVM; RoHS: RoHS; Temperature: -55°C+155°C; Tolerance: 1%; Voltage: NA; Wattage: 1/16W; Weight: 0.65mg; Datasheet: Y:\MIS_DATABASE\DATASHEETS\RESISTORS\RCXXXXL-SER_MAR18.PDF
R270 = RESISTOR: RES 2.49K 1/16W 1% 0402; Chkd/date: VASANTHA/270516; Crtd /date: VASANTHA/270516; Custom_Duty: 15%; Customs_HS_Code: 85332119; Distributor_name: DIGIKEY; Distributor_part_number: 311-2.49KLRCT-ND; Footprint Path: Y:\MIS_DATABASE\Library\ALTIUM_TOOL\PCB_FOOTPRINTS\Altium_Footprint_Lib.PcbLib; Height: 0.40MM; Library Path: Y:\MIS_DATABASE\Library\ALTIUM_TOOL\SCHEMATICS_PARTS\MS_DISCRETE_Library.schlib; Mfr_name: YAGEO AMERICA; Mfr_part_number: RC0402FR-072K49L; Mistral Part No: 110016050020-R; Package: 0402; Part_type: RESISTORS\FIXED; Project: TMDXCSKCC; RoHS: RoHS; Temperature: -55°C+155°C; Tolerance: 1%; Voltage: NA; Wattage: 1/16W; Weight: 0.65mg; Datasheet: Y:\MIS_DATABASE\DATASHEETS\RESISTORS\RCXXXXL-SER_MAR18.PDF
R289-R292 = RESISTOR: RES 49.9E 1/16W 1% 0402; Chkd/date: JEBRAN/050815; Crtd /date: JEBRAN/050815; Custom_Duty: 15%; Customs_HS_Code: 85332119; Distributor_name: DIGIKEY; Distributor_part_number: 311-49.9LRCT-ND; Footprint Path: Y:\MIS_DATABASE\Library\ALTIUM_TOOL\PCB_FOOTPRINTS\Altium_Footprint_Lib.PcbLib; Height: 0.40MM; Library Path: Y:\MIS_DATABASE\Library\ALTIUM_TOOL\SCHEMATICS_PARTS\MS_DISCRETE_Library.schlib; Mfr_name: YAGEO AMERICA; Mfr_part_number: RC0402FR-0749R9L; Mistral Part No: 110009030846-R; Package: 0402; Part_type: RESISTORS\FIXED; Project: PDLU; RoHS: RoHS; SIGNAL_MODEL: DEFAULT_RESISTOR_49.9OHM_1_2; Temperature: -55°C+155°C; Tolerance: 1%; Voltage: NA; Wattage: 1/16W; Weight: 0.65mg; Datasheet: Y:\MIS_DATABASE\DATASHEETS\RESISTORS\RCXXXXL-SER_MAR18.PDF
TP21 = TESTPOINT: TESTPOINT CIR 40 SMD; Chkd/date: MAZHAR/190505; Crtd /date: MAZHAR/190505; Distributor_name: NA; Distributor_part_number: NA; Footprint Path: Y:\MIS_DATABASE\Library\ALTIUM_TOOL\PCB_FOOTPRINTS\Altium_Footprint_Lib.PcbLib; Height: NA; Library Path: Y:\MIS_DATABASE\Library\ALTIUM_TOOL\SCHEMATICS_PARTS\MS_DISCRETE_Library.schlib; MECHANICAL 3D STEP FILE: NA; Mfr_name: LOCAL; Mistral Part No: 130009030933; Package: SMD; Project: RAINIER-3; RoHS: NA; Temperature: NA; Tolerance: NA; Voltage: NA; Wattage: NA; Weight: NA; Datasheet: NA
U39 = SN74LVC1G08DBVRE4_SOT23-5: IC SINGLE 2-INPUT POSITIVE AND GATE SOT23-5; Chkd/date: SUHAS/221010; Crtd /date: USMAN/151008; Custom_Duty: 15%; Customs_HS_Code: 85423100; Distributor_name: DIGIKEY; Distributor_part_number: SN74LVC1G08DBVRE4-ND; Height: 1.45MM; Mfr_name: TEXAS INSTRUMENTS; Mistral Part No: 141009060026-R; Part_type: ICS\DIGITAL\GATES; Project: KHAN_MAIN; RoHS: Sb/ Br FREE; Temperature: -40°C+85°C; Datasheet: Y:\MIS_DATABASE\DATASHEETS\ICS\DIGITAL\GATES\SN74LVC1G08.PDF
U40 = DP83822HF_QFN32: IC ROBUST 10/100 Mbps ETHERNET PHY LAYER TRANSCEIVER VQFN32; Chkd/date: MANIRAJA/200218; Crtd /date: MANIRAJA/200218; Custom_Duty: 15%; Customs_HS_Code: 85423100; Distributor_name: DIGIKEY; Distributor_part_number: 296-44795-1-ND; Footprint Path: Y:\MIS_DATABASE\Library\ALTIUM_TOOL\PCB_FOOTPRINTS\Altium_Footprint_Lib.PcbLib; Height: 1.00MM; Library Path: Y:\MIS_DATABASE\Library\ALTIUM_TOOL\SCHEMATICS_PARTS\MS_TELECOM_Library.schlib; Mfr_name: TEXAS INSTRUMENTS; Mistral Part No: 143018020002-R; Package: VQFN32; Part_type: ICS\TELECOM\TRANSCEIVER; Project: TI_SVB_MAXWELL_FMB; RoHS: RoHS; Temperature: -40°C+85°C; Tolerance: NA; Voltage: NA; Wattage: NA; Weight: NA; Datasheet: Y:\MIS_DATABASE\DATASHEETS\ICS\DIGITAL\BUSTRANSCEIVER\DP83822XX.PDF
Y5 = CRY: CRY 25.000MHz 18pF SMD; Chkd/date: VASANTHA/110316; Crtd /date: JEBRAN/090216; Custom_Duty: 24%; Customs_HS_Code: 85439000; Distributor_name: DIGIKEY; Distributor_part_number: CTX1175CT-ND; Footprint Path: Y:\MIS_DATABASE\Library\ALTIUM_TOOL\PCB_FOOTPRINTS\Altium_Footprint_Lib.PcbLib; Height: 1.35MM; Library Path: Y:\MIS_DATABASE\Library\ALTIUM_TOOL\SCHEMATICS_PARTS\MS_DISCRETE_Library.schlib; Mfr_name: CTS; Mfr_part_number: 445I23D25M00000; Mistral Part No: 130016020016-R; Package: SMD; Part_type: CRYSTAL; Project: PDI_MINIPCB; RoHS: RoHS; Temperature: -40°C+85°C; Tolerance: NA; Voltage: NA; Wattage: NA; Weight: 50mg; Datasheet: Y:\MIS_DATABASE\DATASHEETS\MISC\CRY_OSC\445.PDF
C109 C110 C121-C123 = CAP: CAP CERAMIC 1uF 16V 10% X5R 0402; Chkd/date: MANIRAJA/260618; Crtd /date: ALVY/260618; Custom_Duty: 15%; Customs_HS_Code: 85322990; Distributor_name: DIGIKEY; Distributor_part_number: 445-13181-1-ND; Footprint Path: Y:\MIS_DATABASE\Library\ALTIUM_TOOL\PCB_FOOTPRINTS\Altium_Footprint_Lib.PcbLib; Height: 0.33MM; Library Path: Y:\MIS_DATABASE\Library\ALTIUM_TOOL\SCHEMATICS_PARTS\MS_DISCRETE_Library.schlib; Mfr_name: TDK CORPORATION; Mfr_part_number: CGB2A1X5R1C105K033BC; Mistral Part No: 120018060036-R; Package: 0402; Part_type: CAPACITORS\CERAMIC; Project: MYTHIC_PCIE_DB; RoHS: RoHS; Temperature: -55°C+85°C; Tolerance: 10%; Voltage: 16V; Wattage: NA; Weight: 0.65mg; Datasheet: Y:\MIS_DATABASE\DATASHEETS\CAPACITORS\TDK-CG-SER.PDF
C116 C125 C126 = CAP: CAP CERAMIC 10uF 10V 20% X5R 0402; Chkd/date: VASANTHA/291216; Crtd /date: USMAN/261113; Custom_Duty: 15%; Customs_HS_Code: 85322990; Distributor_name: DIGIKEY; Distributor_part_number: 1276-1450-1-ND; Footprint Path: Y:\MIS_DATABASE\Library\ALTIUM_TOOL\PCB_FOOTPRINTS\Altium_Footprint_Lib.PcbLib; Height: 0.55MM; Library Path: Y:\MIS_DATABASE\Library\ALTIUM_TOOL\SCHEMATICS_PARTS\MS_DISCRETE_Library.schlib; Mfr_name: SAMSUNG; Mfr_part_number: CL05A106MP5NUNC; Mistral Part No: 120013110019-R; Package: 0402; Part_type: CAPACITORS\CERAMIC; Project: C-BAND_SYNTH; RoHS: RoHS; Temperature: -55°C+85°C; Tolerance: 20%; Voltage: 10V; Wattage: NA; Weight: 0.65mg; Datasheet: Y:\MIS_DATABASE\DATASHEETS\CAPACITORS\CL05A106MP5NUNC.PDF
C117 C127 C128 = CAP: CAP CERAMIC 0.01uF 25V 10% X8R 0402; Assembly_Instruction: DNI; Chkd/date: MANIRAJA/061218; Crtd /date: ALVY/061218; Custom_Duty: 15%; Customs_HS_Code: 85322990; Distributor_name: DIGIKEY; Distributor_part_number: 445-173657-1-ND; Footprint Path: Y:\MIS_DATABASE\Library\ALTIUM_TOOL\PCB_FOOTPRINTS\Altium_Footprint_Lib.PcbLib; Height: 0.60MM; Library Path: Y:\MIS_DATABASE\Library\ALTIUM_TOOL\SCHEMATICS_PARTS\MS_DISCRETE_Library.schlib; Mfr_name: TDK CORPORATION; Mfr_part_number: C1005X8R1E103K050BE; Mistral Part No: 120009030012-R; Package: 0402; Part_type: CAPACITORS\CERAMIC; Project: RFSU_POC-CARD; RoHS: RoHS; Temperature: -55°C+150°C; Tolerance: 10%; Voltage: 25V; Wattage: NA; Weight: 0.65mg; Datasheet: Y:\MIS_DATABASE\DATASHEETS\CAPACITORS\TDK-CAP-E-SER.PDF
C120 = CAP: CAP CERAMIC 4.7uF 25V 10% X6S 0603; Chkd/date: MANIRAJA/241018; Crtd /date: ALVY/241018; Custom_Duty: 15%; Customs_HS_Code: 85322990; Distributor_name: DIGIKEY; Distributor_part_number: 490-7199-1-ND; Footprint Path: Y:\MIS_DATABASE\Library\ALTIUM_TOOL\PCB_FOOTPRINTS\Altium_Footprint_Lib.PcbLib; Height: 1.00MM; Library Path: Y:\MIS_DATABASE\Library\ALTIUM_TOOL\SCHEMATICS_PARTS\MS_DISCRETE_Library.schlib; Mfr_name: MURATA; Mfr_part_number: GRM188C81E475KE11D; Mistral Part No: 120018100056-R; Package: 0603; Part_type: CAPACITORS\CERAMIC; Project: TI_J7ES_EVM_CP; RoHS: RoHS; Temperature: -55°C+105°C; Tolerance: 10%; Voltage: 25V; Wattage: NA; Weight: 6.3mg; Datasheet: Y:\MIS_DATABASE\DATASHEETS\CAPACITORS\GRM188C81E475KE11D.PDF
R6 = RESISTOR: RES 2.87K 1/10W 1% 0402; Chkd/date: VASANTHA/160215; Crtd /date: MAZHAR/240809; Custom_Duty: 15%; Customs_HS_Code: 85332119; Distributor_name: DIGIKEY; Distributor_part_number: P2.87KLCT-ND; Footprint Path: Y:\MIS_DATABASE\Library\ALTIUM_TOOL\PCB_FOOTPRINTS\Altium_Footprint_Lib.PcbLib; Height: 0.40MM; Library Path: Y:\MIS_DATABASE\Library\ALTIUM_TOOL\SCHEMATICS_PARTS\MS_DISCRETE_Library.schlib; Mfr_name: PANASONIC-ECG; Mfr_part_number: ERJ-2RKF2871X; Mistral Part No: 110009080021-R; Package: 0402; Part_type: RESISTORS\FIXED; Project: VMEFMCD; RoHS: RoHS; Temperature: -55°C+155°C; Tolerance: 1%; Voltage: NA; Wattage: 1/10W; Weight: 0.8mg; Datasheet: Y:\MIS_DATABASE\DATASHEETS\RESISTORS\PAN-ERJSER_NOV17.PDF
R8 = RESISTOR: RES 1.69K 1/10W 1% 0402; Chkd/date: SHREESHAIL/121205; Crtd /date: MAZHAR/180705; Custom_Duty: 15%; Customs_HS_Code: 85332119; Distributor_name: DIGIKEY; Distributor_part_number: P1.69KLCT-ND; Footprint Path: Y:\MIS_DATABASE\Library\ALTIUM_TOOL\PCB_FOOTPRINTS\Altium_Footprint_Lib.PcbLib; Height: 0.40MM; Library Path: Y:\MIS_DATABASE\Library\ALTIUM_TOOL\SCHEMATICS_PARTS\MS_DISCRETE_Library.schlib; Mfr_name: PANASONIC-ECG; Mfr_part_number: ERJ-2RKF1691X; Mistral Part No: 110009030133-R; Package: 0402; Part_type: RESISTORS\FIXED; Project: PMP-VIOMEDIA; RoHS: RoHS; Temperature: -55°C+155°C; Tolerance: 1%; Voltage: NA; Wattage: 1/10W; Weight: 0.8mg; Datasheet: Y:\MIS_DATABASE\DATASHEETS\RESISTORS\PAN-ERJSER_NOV17.PDF
R9 = RESISTOR: RES 4.53K 1/16W 1% 0402; Chkd/date: VASANTHA/201216; Crtd /date: USMAN/290709; Custom_Duty: 15%; Customs_HS_Code: 85332119; Distributor_name: DIGIKEY; Distributor_part_number: 541-4.53KLCT-ND; Footprint Path: Y:\MIS_DATABASE\Library\ALTIUM_TOOL\PCB_FOOTPRINTS\Altium_Footprint_Lib.PcbLib; Height: 0.40MM; Library Path: Y:\MIS_DATABASE\Library\ALTIUM_TOOL\SCHEMATICS_PARTS\MS_DISCRETE_Library.schlib; Mfr_name: VISHAY; Mfr_part_number: CRCW04024K53FKED; Mistral Part No: 110016060008-R; Package: 0402; Part_type: RESISTORS\FIXED; Project: VMEFMCD; RoHS: RoHS; Temperature: -55°C+155°C; Tolerance: 1%; Voltage: NA; Wattage: 1/16W; Weight: 0.65mg; Datasheet: Y:\MIS_DATABASE\DATASHEETS\RESISTORS\CRCW0603.PDF
R160 R176 = RESISTOR: RES 3.57K 1/16W 1% 0402; Chkd/date: VASANTHA/281216; Crtd /date: USMAN/300709; Custom_Duty: 15%; Customs_HS_Code: 85332119; Distributor_name: DIGIKEY; Distributor_part_number: 541-3.57KLCT-ND; Footprint Path: Y:\MIS_DATABASE\Library\ALTIUM_TOOL\PCB_FOOTPRINTS\Altium_Footprint_Lib.PcbLib; Height: 0.40MM; Library Path: Y:\MIS_DATABASE\Library\ALTIUM_TOOL\SCHEMATICS_PARTS\MS_DISCRETE_Library.schlib; Mfr_name: VISHAY; Mfr_part_number: CRCW04023K57FKED; Mistral Part No: 110009070012-R; Package: 0402; Part_type: RESISTORS\FIXED; Project: VMEFMCD; RoHS: RoHS; Temperature: -55°C+155°C; Tolerance: 1%; Voltage: NA; Wattage: 1/16W; Weight: 0.65mg; Datasheet: Y:\MIS_DATABASE\DATASHEETS\RESISTORS\CRCW0603.PDF
R177 = RESISTOR: RES 1.13K 1/16W 1% 0402; Chkd/date: MAZHAR/310709; Crtd /date: USMAN/300709; Custom_Duty: 15%; Customs_HS_Code: 85332119; Distributor_name: DIGIKEY; Distributor_part_number: 541-1.13KLCT-ND; Footprint Path: Y:\MIS_DATABASE\Library\ALTIUM_TOOL\PCB_FOOTPRINTS\Altium_Footprint_Lib.PcbLib; Height: 0.40MM; Library Path: Y:\MIS_DATABASE\Library\ALTIUM_TOOL\SCHEMATICS_PARTS\MS_DISCRETE_Library.schlib; Mfr_name: VISHAY; Mfr_part_number: CRCW04021K13FKED; Mistral Part No: 110009070011-R; Package: 0402; Part_type: RESISTORS\FIXED; Project: VMEFMCD; RoHS: RoHS; Temperature: -55°C+155°C; Tolerance: 1%; Voltage: NA; Wattage: 1/16W; Weight: 0.65mg; Datasheet: Y:\MIS_DATABASE\DATASHEETS\RESISTORS\CRCW0603.PDF
TP1-TP3 TP6 TP8-TP10 TP18-TP20 = TESTPOINT: TESTPOINT 1.0MM DRILL PTH; Chkd/date: MAZHAR/271211; Crtd /date: SHREESHAIL/041005; Distributor_name: NA; Distributor_part_number: NA; Height: NA; Mfr_name: LOCAL; Mistral Part No: 130009030938; Package: THRU-HOLE; Project: HSE; Datasheet: NA
U25 U27 U28 = TPS74801DRCR_SON10: IC 1.5A ADJUSTABLE LDO VOLTAGE REGULATOR WITH PROG SOFT-START VSON10; Chkd/date: MANIRAJA/190218; Crtd /date: USMAN/191208; Custom_Duty: 15%; Customs_HS_Code: 85423100; Distributor_name: DIGIKEY; Distributor_part_number: 296-21563-1-ND; Footprint Path: Y:\MIS_DATABASE\Library\ALTIUM_TOOL\PCB_FOOTPRINTS\Altium_Footprint_Lib.PcbLib; Height: 1.00MM; Library Path: Y:\MIS_DATABASE\Library\ALTIUM_TOOL\SCHEMATICS_PARTS\MS_MISCPOWER_Library.schlib; Mfr_name: TEXAS INSTRUMENTS; Mistral Part No: 142009030403-R; Package: VSON10; Part_type: ICS\POWER\VOLTAGE REGULATOR; Project: BSN-II; RoHS: RoHS; Temperature: -40°C+125°C; Tolerance: NA; Voltage: NA; Wattage: NA; Weight: 26.1mg; Datasheet: Y:\MIS_DATABASE\DATASHEETS\MISC\REGULATORS\TPS748XX.PDF

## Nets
DGND: C60.2 C61.2 C109.2 C110.2 C111.1 C116.2 C117.2 C118.1 C119.1 C120.1 C121.2 C122.2 C123.2 C124.1 C125.2 C126.2 C127.2 C128.2 C129.1 C130.1 C174.2 C176.2 C177.2 C178.1 C179.1 C180.2 C181.2 C182.2 C183.2 C186.2 C187.1 C188.1 C189.2 C190.2 J19.5 J19.6 J23.1(CH-GND) J24.22 J24.39 J24.40 J24.59 J24.60 Q13.2(SOURCE) R6.2 R8.2 R9.2 R94.2 R95.2 R96.2 R97.2 R98.2 R99.2 R100.2 R101.2 R102.2 R259.2 TP1.1(TP) TP3.1(TP) TP18.1(TP) TP19.1(TP) U25.6(GND) U25.11(PAD) U27.6(GND) U27.11(PAD) U28.6(GND) U28.11(PAD) U39.3(GND) U40.33(EP) ; also on sheet 1 2 3 8 9 10 11 12 13 14 15 16 17 18 19 20 21
VCC_3V3: C60.1 C109.1 C111.2 C119.2 C120.2 C121.1 C123.1 C124.2 C174.1 C176.1 C177.1 C180.1 C186.1 C187.2 C188.2 C189.1 FL2.1 FL3.2 J24.1 R87.1 R103.1 R247.2 R257.1 R258.1 R260.1 R261.1 R262.1 R263.1 R265.1 R267.2 R269.2 R270.1 R289.1 R290.1 R291.1 R292.1 TP20.1(TP) U25.1(IN1) U25.2(IN2) U27.1(IN1) U27.2(IN2) U27.4(BIAS) U28.1(IN1) U28.2(IN2) U39.5(VCC) U40.21(VDDIO) ; also on sheet 1 2 3 8 9 10 11 12 13 14 15 16 17 18 19 20
VCC_5V0: C110.1 C122.1 J24.2 TP2.1(TP) U25.4(BIAS) U28.4(BIAS) ; also on sheet 8 17 18 20 21
VCC_12V0: TP10.1(TP) ; also on sheet 1 2 3 8
VDD_1V0: C125.1 C129.2 R177.1 TP8.1(TP) U27.9(OUT1) U27.10(OUT2) ; also on sheet 13 14 15 16
VDD_1V8: C116.1 C118.2 R160.1 TP6.1(TP) U25.9(OUT1) U25.10(OUT2) ; also on sheet 9 13
VDD_2V5: C126.1 C130.2 R7.1 R176.1 TP9.1(TP) U28.9(OUT1) U28.10(OUT2) ; also on sheet 13 14 15 16
BP/MC_PRG1_UART0_RXD: J24.27 ; also on sheet 10 20
BP/MC_PRG1_UART0_TXD: J24.37 ; also on sheet 10 20
ETH_EARTH: J23.15(SH1) J23.16(SH2) ; also on sheet 13 14 15 16
FB_V1V0: R9.1 R177.2 U27.8(FB)
FB_V1V8: R6.1 R160.2 U25.8(FB)
FB_V2V5: R8.1 R176.2 U28.8(FB)
I2C5_SCL: J19.3 J24.47 ; also on sheet 12
I2C5_SDA: J19.1 J24.50 ; also on sheet 12
IMU_GPIO0: J19.7 ; also on sheet 8
IMU_GPIO1: J19.9 ; also on sheet 8
MC_EQEP0_A: J24.46 ; also on sheet 20
MC_EQEP0_B: J24.48 ; also on sheet 20
MC_EQEP0_I: J24.42 ; also on sheet 20
MC_EQEP0_S: J24.44 ; also on sheet 20
MC_PRG1_PWM0_B0: J24.5 ; also on sheet 10
MC_PRG1_PWM0_B1: J24.7 ; also on sheet 10
MC_PRG1_PWM0_B2: J24.12 ; also on sheet 10
MC_PRG1_PWM2_A0: J24.21 ; also on sheet 10
MC_PRG1_PWM2_A1: J24.13 ; also on sheet 10
MC_PRG1_PWM3_A0: J24.25 ; also on sheet 10
MC_PRG1_PWM3_A2: J24.20 ; also on sheet 10
MC_PRG1_PWM3_B0: J24.23 ; also on sheet 10
MC_PRG1_PWM3_B1: J24.16 ; also on sheet 10
MCU_ADC1_AIN0: J24.51 ; also on sheet 20 21
MCU_ADC1_AIN1: J24.53 ; also on sheet 20 21
MCU_ADC1_AIN2: J24.55 ; also on sheet 20 21
MCU_ADC1_AIN3: J24.57 ; also on sheet 20 21
MCU_ADC1_AIN4: J24.56 ; also on sheet 20 21
MCU_ADC1_AIN5: J24.54 ; also on sheet 20 21
MCU_ADC1_AIN6: J24.52 ; also on sheet 20 21
MCU_ADC1_AIN7: J24.49 ; also on sheet 20 21
MCU_ADC_EXT_TRIGGER1: J24.58 ; also on sheet 8
MDIO0_MDC: U40.20(MDC) ; also on sheet 8 12
MDIO0_MDIO: U40.19(MDIO) ; also on sheet 8 12
PG_V2V5: R7.2 U27.5(EN) U28.3(PG)
PRG1_IEP0_EDIO_OUTVALID: J24.41 ; also on sheet 8
PRG1_PRU1_GPO5: J24.9 ; also on sheet 9
PRG1_PWM0_A0: J24.4 ; also on sheet 9
PRG1_PWM0_A1: J24.6 ; also on sheet 9
PRG1_PWM0_A2: J24.8 ; also on sheet 9
PRG1_PWM0_TZ_IN: J24.11 ; also on sheet 9
PRG1_PWM0_TZ_OUT: J24.10 ; also on sheet 9
PRG1_PWM2_B0: J24.19 ; also on sheet 9
PRG1_PWM2_B1: J24.29 ; also on sheet 10 20
PRG1_PWM3_A1: J24.17 ; also on sheet 9
PRG1_PWM3_B2: J24.38 ; also on sheet 8
PRG1_PWM3_TZ_OUT: J24.15 ; also on sheet 9
RMII8_50MHz_REFCLK: R268.1 ; also on sheet 12
RMII8_AVD33: C61.1 C181.1 C182.1 C183.1 FL2.2 U40.14(AVD33)
RMII8_CRS_DV: R96.1 R260.2 U40.27(CRS/CRS_DV/LED_CFG/LED_SPEED) ; also on sheet 8
RMII8_LED0: J23.12 R94.1 R257.2 U40.17(LED_0/GPIO)
RMII8_LED1: Q13.1(GATE) U40.24(LED_1/GPIO)
RMII8_MDI_RD_N: J23.8(MX1-) R292.2 U40.9(RD_M)
RMII8_MDI_RD_P: J23.7(MX1+) R291.2 U40.10(RD_P)
RMII8_MDI_TD_N: J23.10(MX0-) R290.2 U40.11(TD_M)
RMII8_MDI_TD_P: J23.9(MX0+) R289.2 U40.12(TD_P)
RMII8_MODE_XI50: R95.1 R258.2 U40.26(RX_DV/RMII_MODE/XI_50)
RMII8_PHY_INTn: R269.1 U40.8(INT/PWDN_N) ; also on sheet 8
RMII8_PHY_RESET: R248.1 ; also on sheet 8
RMII8_PHYAD0: R98.1 R262.2 TP21.1(TP) U40.29(COL/PHYAD0/FX_EN)
RMII8_PHYAD1: R99.1 R263.2 R264.2 U40.30(RX_D0/PHYAD1/AN_1)
RMII8_PHYAD2: R100.1 R265.2 R266.2 U40.31(RX_D1/PHYAD2/EEE_ON)
RMII8_PHYAD3: R101.1 R267.1 U40.32(RX_D2/PHYAD3/FLD)
RMII8_PHYAD4: R102.1 R268.2 R270.2 U40.1(RX_D3/PHYAD4/AN_EN)
RMII8_RBIAS: R259.1 U40.16(RBIAS)
RMII8_RX_ER: R97.1 R261.2 U40.28(RX_ER/AMDIX_EN) ; also on sheet 8
RMII8_RXD0: R264.1 ; also on sheet 8
RMII8_RXD1: R266.1 ; also on sheet 8
RMII8_SPEED_LED: J23.13 Q13.3(DRAIN)
RMII8_TX_EN: U40.3(TX_EN) ; also on sheet 8
RMII8_TXD0: U40.4(TX_D0) ; also on sheet 8
RMII8_TXD1: U40.5(TX_D1) ; also on sheet 8
RMII8_XI: C178.2 U40.23(XI) Y5.2
RMII8_XO: C179.2 U40.22(XO) Y5.1
SOC_PORZ_OUT: U39.1(A) ; also on sheet 8 13 14 15 16
SPI3_CLK: J24.24 ; also on sheet 8 20
SPI3_CS1: J24.3 ; also on sheet 8 20
SPI3_D0: J24.26 ; also on sheet 8 20
SPI3_D1: J24.28 ; also on sheet 8 20
SPI6_CLK/PRG1_ECAP0_SYNC_OUT: J24.18 ; also on sheet 8
SPI6_CS1/PRG1_PWM3_TZ_IN: J24.30 ; also on sheet 8
SPI6_D0/PRG1_ECAP0_SYNC_IN: J24.14 ; also on sheet 8
SPI6_D1/PRG1_ECAP0_IN_APWM_OUT: J24.36 ; also on sheet 8
UART3_CTSn: J19.10 ; also on sheet 12 20
UART3_RTSn: J19.8 ; also on sheet 12 20
UART3_RX: J19.4 ; also on sheet 9 20
UART3_TX: J19.2 ; also on sheet 9 20
VSYS_IO_3V3: R159.2 R166.1 ; also on sheet 8
N23748372: R247.1 R248.2 U39.2(B)
N23748397: U39.4(Y) U40.18(RESET_N)
N23749024: J23.11 R87.2
N23749026: J23.14 R103.2
N23750460: R166.2 U28.5(EN)
N23750751: C128.1 U28.7(SS)
N23750795: R159.1 U25.5(EN)
N23750890: C127.1 U27.7(SS)
N23750996: C117.1 U25.7(SS)
N23924268: C190.1 FL3.1 J23.2(VCC)

Not connected (* = marked no-connect by the designer): J23 3(MX3+) 4(MX3-) 5(MX2+) 6(MX2-); J24 31 32 33 34 35 43 45; U25 3(PG)*; U27 3(PG)*; U40 2(TX_CLK)* 6(TX_D2)* 7(TX_D3)* 13(NC1)* 15(NC2)* 25(RX_CLK)*

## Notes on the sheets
sheet 22
- RMII8 INTERFACE
- RESET LOGIC
- PHY
- Address
- QSGMII_PHY0
- 10000
- 0x10
- QSGMII_PHY1
- 10001
- 0x11
- QSGMII_PHY2
- 10010
- 0x12
- RESISTOR STRAPPING
- QSGMII_PHY3
- 10011
- 0x13
- PRG0_RGMII1
- 00000
- 0x00
- PRG0_RGMII2
- 00011
- 0x03
- PRG1_RGMII1
- 01100
- 0x0C
- PRG1_RGMII2
- 01111
- 0x0F
- RMII8
- 10111
- 0x17
- PHY ADD : 10111
sheet 23
- POWER SUPPLY
- ETHERNET POWER
- 3.3V to 2.5V LDO
- 3.3V to 1.8V LDO
- 3.3V to 1.0V LDO
- GROUND TEST POINTS
- POWER TEST POINTS
- PCB NOTE:Keep 4.7uF capacitor close to BIAS pin.
sheet 24
- USS/IMU SENSOR HEADER
- Silkscreen for J19:
   "IMU/USS HDR"
- MOTOR CONTROL HEADER
- PR1_PRU0_SD6_D
- PR1_PRU0_SD6_CLK
- PR1_PRU0_SD7_CLK
- PR1_PRU0_SD7_D
- PR1_PRU0_SD8_CLK
- PRG1_IEP0_EDC_SYNC_OUT0
- PRG1_IEP0_EDC_LATCH_IN0
- PR1_PRU0_SD8_D
- PR1_PRU0_ENDAT2_OUT_EN/PR1_PRU0_SD4_CLK
- PR1_PRU0_ENDAT2_CLK/PR1_PRU0_SD3_CLK
- PR1_PRU0_ENDAT2_IN/PR1_PRU0_SD5_D
- PR1_PRU0_ENDAT2_OUT/PR1_PRU0_SD3_D
- PR1_PRU0_ENDAT1_OUT/PR1_PRU0_SD2_CLK
- PR1_PRU0_ENDAT1_CLK/PR1_PRU0_SD1_D
- PR1_PRU0_ENDAT0_OUT_EN/PR1_PRU0_SD1_CLK
- PR1_PRU0_ENDAT0_OUT/PR1_PRU0_SD0_D
- PR1_PRU0_ENDAT0_CLK/PR1_PRU0_SD0_CLK
- PRG1_IEP0_EDIO_DATA_IN_OUT30
- PR1_PRU0_ENDAT1_IN/PR1_PRU0_SD5_CLK/PRG1_IEP0_EDIO_DATA_IN_OUT29
- PR1_PRU0_ENDAT0_IN/PR1_PRU0_SD4_D/PRG1_IEP0_EDIO_DATA_IN_OUT28
- PRG1_IEP0_EDIO_DATA_IN_OUT31
- PR1_PRU0_ENDAT1_OUT_EN/PR1_PRU0_SD2_D
- Silkscreen for J24:
   "MOTOR CNTRL HDR"
